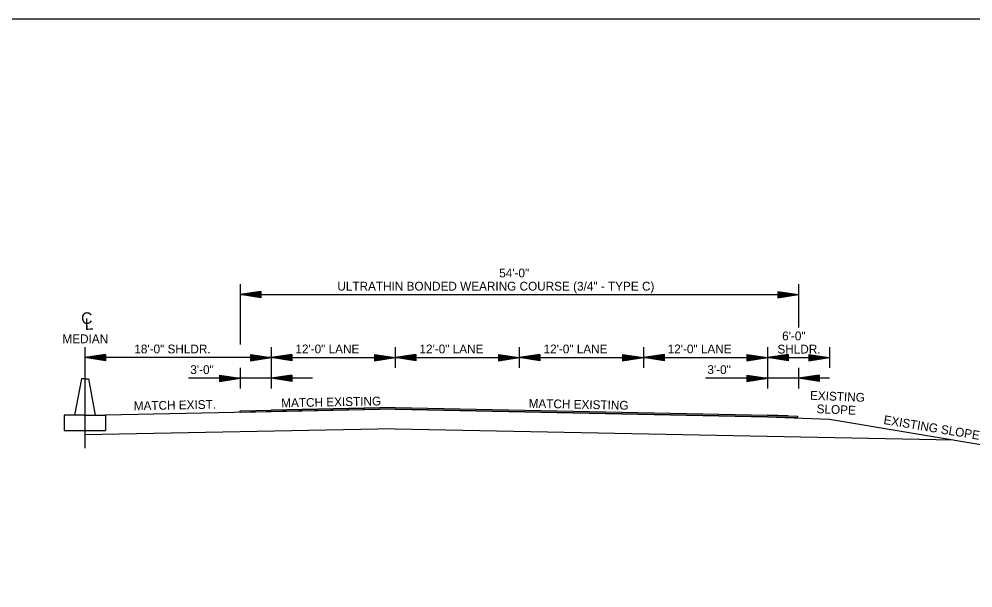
# Model space of a CAD drawing. Extents: x 2261938 to 2263136, y -3124572 to -3124216.
# Drawn here: x 2262374.3 to 2262466.5, y -3124501.1 to -3124446.1 of the extents above; entities that cross this region are included whole.
import ezdxf

# ---------------------------------------------------------------- set-up
doc = ezdxf.new("R2010")
doc.units = 0
for name, color, linetype in [('DSN_DRFT_Common-Annotations', 7, 'Continuous'), ('DSN_DRFT_Common-Line', 7, 'Continuous'), ('DSN_DRFT_Dimension', 7, 'Continuous')]:
    doc.layers.add(name, color=color, linetype=linetype)

msp = doc.modelspace()

# ---------------------------------------------------------------- linework, layer by layer
at = {"layer": 'DSN_DRFT_Common-Line'}
for p, q in [((2262395.658, -3124471.75), (2262395.658, -3124477.576)), ((2262449.658, -3124471.75), (2262449.658, -3124475.924)), ((2262380.658, -3124477.836), (2262380.658, -3124487.585)), ((2262398.658, -3124477.836), (2262398.658, -3124481.836)), ((2262410.658, -3124477.836), (2262410.658, -3124479.836)), ((2262422.658, -3124477.836), (2262422.658, -3124479.836)), ((2262434.658, -3124477.836), (2262434.658, -3124479.836)), ((2262446.658, -3124477.836), (2262446.658, -3124481.836)), ((2262452.658, -3124477.836), (2262452.658, -3124479.836)), ((2262395.658, -3124479.836), (2262395.658, -3124481.836)), ((2262398.658, -3124479.836), (2262398.658, -3124481.836)), ((2262449.658, -3124479.836), (2262449.658, -3124481.836)), ((2262380.325, -3124480.896), (2262379.658, -3124484.396)), ((2262380.658, -3124480.896), (2262380.325, -3124480.896)), ((2262380.658, -3124480.896), (2262380.991, -3124480.896)), ((2262380.991, -3124480.896), (2262381.658, -3124484.396)), ((2262410.658, -3124483.836), (2262382.658, -3124484.396)), ((2262410.658, -3124483.669), (2262398.658, -3124483.909)), ((2262410.658, -3124483.669), (2262446.658, -3124484.389)), ((2262410.658, -3124483.836), (2262446.658, -3124484.556)), ((2262380.658, -3124484.396), (2262378.658, -3124484.396)), ((2262378.658, -3124484.396), (2262378.658, -3124485.896)), ((2262380.658, -3124484.396), (2262382.658, -3124484.396)), ((2262382.658, -3124484.396), (2262382.658, -3124485.896)), ((2262446.658, -3124484.556), (2262452.658, -3124484.796)), ((2262449.551, -3124484.505), (2262449.545, -3124484.671)), ((2262452.658, -3124484.796), (2262472.658, -3124488.129)), ((2262378.658, -3124485.896), (2262382.658, -3124485.896)), ((2262410.658, -3124485.711), (2262380.658, -3124486.311)), ((2262410.658, -3124485.711), (2262464.625, -3124486.79))]:
    msp.add_line(p, q, dxfattribs=at)
for points in [[(2262328.106, -3124446.104), (2262328.106, -3124556.104), (2262498.106, -3124556.104), (2262498.106, -3124446.104)], [(2262446.658, -3124484.556), (2262410.658, -3124483.836), (2262398.658, -3124484.076), (2262395.658, -3124484.136), (2262395.658, -3124483.967), (2262398.658, -3124483.909), (2262410.658, -3124483.669), (2262446.658, -3124484.389), (2262449.551, -3124484.505), (2262449.545, -3124484.671)]]:
    msp.add_lwpolyline(points, close=True, dxfattribs=at)
msp.add_lwpolyline([(2262448.658, -3124484.469), (2262446.658, -3124484.389), (2262448.658, -3124484.469), (2262449.551, -3124484.505)], dxfattribs=at)
at = {"layer": 'DSN_DRFT_Dimension'}
for p, q in [((2262397.658, -3124472.45), (2262395.658, -3124472.75)), ((2262397.658, -3124473.05), (2262395.658, -3124472.75)), ((2262395.658, -3124472.75), (2262449.658, -3124472.75)), ((2262397.658, -3124472.5), (2262395.992, -3124472.75)), ((2262397.658, -3124473), (2262395.992, -3124472.75)), ((2262397.658, -3124472.551), (2262396.336, -3124472.75)), ((2262397.658, -3124472.949), (2262396.336, -3124472.75)), ((2262397.658, -3124472.601), (2262396.669, -3124472.75)), ((2262397.658, -3124472.899), (2262396.669, -3124472.75)), ((2262397.658, -3124472.653), (2262397.008, -3124472.75)), ((2262397.658, -3124472.848), (2262397.008, -3124472.75)), ((2262397.658, -3124472.703), (2262397.342, -3124472.75)), ((2262397.658, -3124472.797), (2262397.342, -3124472.75)), ((2262397.658, -3124472.45), (2262397.658, -3124473.05)), ((2262447.658, -3124472.45), (2262449.658, -3124472.75)), ((2262447.658, -3124472.45), (2262447.658, -3124473.05)), ((2262447.658, -3124472.5), (2262449.324, -3124472.75)), ((2262447.658, -3124472.551), (2262448.98, -3124472.75)), ((2262447.658, -3124472.601), (2262448.647, -3124472.75)), ((2262447.658, -3124472.653), (2262448.308, -3124472.75)), ((2262447.658, -3124472.703), (2262447.974, -3124472.75)), ((2262447.658, -3124473.05), (2262449.658, -3124472.75)), ((2262447.658, -3124472.848), (2262448.308, -3124472.75)), ((2262447.658, -3124472.949), (2262448.98, -3124472.75)), ((2262447.658, -3124473), (2262449.324, -3124472.75)), ((2262447.658, -3124472.899), (2262448.647, -3124472.75)), ((2262447.658, -3124472.797), (2262447.974, -3124472.75)), ((2262382.658, -3124478.536), (2262380.658, -3124478.836)), ((2262398.658, -3124478.836), (2262380.658, -3124478.836)), ((2262382.658, -3124479.136), (2262380.658, -3124478.836)), ((2262382.658, -3124478.586), (2262380.992, -3124478.836)), ((2262382.658, -3124479.086), (2262380.992, -3124478.836)), ((2262382.658, -3124478.637), (2262381.336, -3124478.836)), ((2262382.658, -3124479.035), (2262381.336, -3124478.836)), ((2262382.658, -3124478.687), (2262381.669, -3124478.836)), ((2262382.658, -3124478.985), (2262381.669, -3124478.836)), ((2262382.658, -3124478.739), (2262382.008, -3124478.836)), ((2262382.658, -3124478.934), (2262382.008, -3124478.836)), ((2262382.658, -3124478.789), (2262382.342, -3124478.836)), ((2262382.658, -3124478.883), (2262382.342, -3124478.836)), ((2262382.658, -3124478.536), (2262382.658, -3124479.136)), ((2262396.658, -3124478.536), (2262398.658, -3124478.836)), ((2262396.658, -3124478.536), (2262396.658, -3124479.136)), ((2262396.658, -3124478.586), (2262398.324, -3124478.836)), ((2262396.658, -3124478.637), (2262397.98, -3124478.836)), ((2262396.658, -3124478.687), (2262397.647, -3124478.836)), ((2262396.658, -3124478.739), (2262397.308, -3124478.836)), ((2262396.658, -3124478.789), (2262396.974, -3124478.836)), ((2262396.658, -3124479.136), (2262398.658, -3124478.836)), ((2262396.658, -3124478.934), (2262397.308, -3124478.836)), ((2262396.658, -3124479.035), (2262397.98, -3124478.836)), ((2262396.658, -3124479.086), (2262398.324, -3124478.836)), ((2262396.658, -3124478.985), (2262397.647, -3124478.836)), ((2262396.658, -3124478.883), (2262396.974, -3124478.836)), ((2262400.658, -3124478.536), (2262398.658, -3124478.836)), ((2262398.658, -3124478.836), (2262410.658, -3124478.836)), ((2262400.658, -3124479.136), (2262398.658, -3124478.836)), ((2262400.658, -3124478.586), (2262398.992, -3124478.836)), ((2262400.658, -3124479.086), (2262398.992, -3124478.836)), ((2262400.658, -3124478.637), (2262399.336, -3124478.836)), ((2262400.658, -3124479.035), (2262399.336, -3124478.836)), ((2262400.658, -3124478.687), (2262399.669, -3124478.836)), ((2262400.658, -3124478.985), (2262399.669, -3124478.836)), ((2262400.658, -3124478.739), (2262400.008, -3124478.836)), ((2262400.658, -3124478.934), (2262400.008, -3124478.836)), ((2262400.658, -3124478.789), (2262400.342, -3124478.836)), ((2262400.658, -3124478.883), (2262400.342, -3124478.836)), ((2262400.658, -3124478.536), (2262400.658, -3124479.136)), ((2262408.658, -3124478.536), (2262410.658, -3124478.836)), ((2262408.658, -3124478.536), (2262408.658, -3124479.136)), ((2262408.658, -3124478.586), (2262410.324, -3124478.836)), ((2262408.658, -3124478.637), (2262409.98, -3124478.836)), ((2262408.658, -3124478.687), (2262409.647, -3124478.836)), ((2262408.658, -3124478.739), (2262409.308, -3124478.836)), ((2262408.658, -3124478.789), (2262408.974, -3124478.836)), ((2262408.658, -3124479.136), (2262410.658, -3124478.836)), ((2262408.658, -3124478.934), (2262409.308, -3124478.836)), ((2262408.658, -3124479.035), (2262409.98, -3124478.836)), ((2262408.658, -3124479.086), (2262410.324, -3124478.836)), ((2262408.658, -3124478.985), (2262409.647, -3124478.836)), ((2262408.658, -3124478.883), (2262408.974, -3124478.836)), ((2262412.658, -3124478.536), (2262410.658, -3124478.836)), ((2262410.658, -3124478.836), (2262422.658, -3124478.836)), ((2262412.658, -3124479.136), (2262410.658, -3124478.836)), ((2262412.658, -3124478.586), (2262410.992, -3124478.836)), ((2262412.658, -3124479.086), (2262410.992, -3124478.836)), ((2262412.658, -3124478.637), (2262411.336, -3124478.836)), ((2262412.658, -3124479.035), (2262411.336, -3124478.836)), ((2262412.658, -3124478.687), (2262411.669, -3124478.836)), ((2262412.658, -3124478.985), (2262411.669, -3124478.836)), ((2262412.658, -3124478.739), (2262412.008, -3124478.836)), ((2262412.658, -3124478.934), (2262412.008, -3124478.836)), ((2262412.658, -3124478.789), (2262412.342, -3124478.836)), ((2262412.658, -3124478.883), (2262412.342, -3124478.836)), ((2262412.658, -3124478.536), (2262412.658, -3124479.136)), ((2262420.658, -3124478.536), (2262422.658, -3124478.836)), ((2262420.658, -3124478.536), (2262420.658, -3124479.136)), ((2262420.658, -3124478.586), (2262422.324, -3124478.836)), ((2262420.658, -3124478.637), (2262421.98, -3124478.836)), ((2262420.658, -3124478.687), (2262421.647, -3124478.836)), ((2262420.658, -3124478.739), (2262421.308, -3124478.836)), ((2262420.658, -3124478.789), (2262420.974, -3124478.836)), ((2262420.658, -3124479.136), (2262422.658, -3124478.836)), ((2262420.658, -3124478.934), (2262421.308, -3124478.836)), ((2262420.658, -3124479.035), (2262421.98, -3124478.836)), ((2262420.658, -3124479.086), (2262422.324, -3124478.836)), ((2262420.658, -3124478.985), (2262421.647, -3124478.836)), ((2262420.658, -3124478.883), (2262420.974, -3124478.836)), ((2262424.658, -3124478.536), (2262422.658, -3124478.836)), ((2262422.658, -3124478.836), (2262434.658, -3124478.836)), ((2262424.658, -3124479.136), (2262422.658, -3124478.836)), ((2262424.658, -3124478.586), (2262422.992, -3124478.836)), ((2262424.658, -3124479.086), (2262422.992, -3124478.836)), ((2262424.658, -3124478.637), (2262423.336, -3124478.836)), ((2262424.658, -3124479.035), (2262423.336, -3124478.836)), ((2262424.658, -3124478.687), (2262423.669, -3124478.836)), ((2262424.658, -3124478.985), (2262423.669, -3124478.836)), ((2262424.658, -3124478.739), (2262424.008, -3124478.836)), ((2262424.658, -3124478.934), (2262424.008, -3124478.836)), ((2262424.658, -3124478.789), (2262424.342, -3124478.836)), ((2262424.658, -3124478.883), (2262424.342, -3124478.836)), ((2262424.658, -3124478.536), (2262424.658, -3124479.136)), ((2262432.658, -3124478.536), (2262434.658, -3124478.836)), ((2262432.658, -3124478.536), (2262432.658, -3124479.136)), ((2262432.658, -3124478.586), (2262434.324, -3124478.836)), ((2262432.658, -3124478.637), (2262433.98, -3124478.836)), ((2262432.658, -3124478.687), (2262433.647, -3124478.836)), ((2262432.658, -3124478.739), (2262433.308, -3124478.836)), ((2262432.658, -3124478.789), (2262432.974, -3124478.836)), ((2262432.658, -3124479.136), (2262434.658, -3124478.836)), ((2262432.658, -3124478.934), (2262433.308, -3124478.836)), ((2262432.658, -3124479.035), (2262433.98, -3124478.836)), ((2262432.658, -3124479.086), (2262434.324, -3124478.836)), ((2262432.658, -3124478.985), (2262433.647, -3124478.836)), ((2262432.658, -3124478.883), (2262432.974, -3124478.836)), ((2262436.658, -3124478.536), (2262434.658, -3124478.836)), ((2262434.658, -3124478.836), (2262446.658, -3124478.836)), ((2262436.658, -3124479.136), (2262434.658, -3124478.836)), ((2262436.658, -3124478.586), (2262434.992, -3124478.836)), ((2262436.658, -3124479.086), (2262434.992, -3124478.836)), ((2262436.658, -3124478.637), (2262435.336, -3124478.836)), ((2262436.658, -3124479.035), (2262435.336, -3124478.836)), ((2262436.658, -3124478.687), (2262435.669, -3124478.836)), ((2262436.658, -3124478.985), (2262435.669, -3124478.836)), ((2262436.658, -3124478.739), (2262436.008, -3124478.836)), ((2262436.658, -3124478.934), (2262436.008, -3124478.836)), ((2262436.658, -3124478.789), (2262436.342, -3124478.836)), ((2262436.658, -3124478.883), (2262436.342, -3124478.836)), ((2262436.658, -3124478.536), (2262436.658, -3124479.136)), ((2262444.658, -3124478.536), (2262446.658, -3124478.836)), ((2262444.658, -3124478.536), (2262444.658, -3124479.136)), ((2262444.658, -3124478.586), (2262446.324, -3124478.836)), ((2262444.658, -3124478.637), (2262445.98, -3124478.836)), ((2262444.658, -3124478.687), (2262445.647, -3124478.836)), ((2262444.658, -3124478.739), (2262445.308, -3124478.836)), ((2262444.658, -3124478.789), (2262444.974, -3124478.836)), ((2262444.658, -3124479.136), (2262446.658, -3124478.836)), ((2262444.658, -3124478.934), (2262445.308, -3124478.836)), ((2262444.658, -3124479.035), (2262445.98, -3124478.836)), ((2262444.658, -3124479.086), (2262446.324, -3124478.836)), ((2262444.658, -3124478.985), (2262445.647, -3124478.836)), ((2262444.658, -3124478.883), (2262444.974, -3124478.836)), ((2262448.658, -3124478.536), (2262446.658, -3124478.836)), ((2262446.658, -3124478.836), (2262452.658, -3124478.836)), ((2262448.658, -3124479.136), (2262446.658, -3124478.836)), ((2262448.658, -3124478.586), (2262446.992, -3124478.836)), ((2262448.658, -3124479.086), (2262446.992, -3124478.836)), ((2262448.658, -3124478.637), (2262447.336, -3124478.836)), ((2262448.658, -3124479.035), (2262447.336, -3124478.836)), ((2262448.658, -3124478.687), (2262447.669, -3124478.836)), ((2262448.658, -3124478.985), (2262447.669, -3124478.836)), ((2262448.658, -3124478.739), (2262448.008, -3124478.836)), ((2262448.658, -3124478.934), (2262448.008, -3124478.836)), ((2262448.658, -3124478.789), (2262448.342, -3124478.836)), ((2262448.658, -3124478.883), (2262448.342, -3124478.836)), ((2262448.658, -3124478.536), (2262448.658, -3124479.136)), ((2262450.658, -3124478.536), (2262452.658, -3124478.836)), ((2262450.658, -3124478.536), (2262450.658, -3124479.136)), ((2262450.658, -3124478.586), (2262452.324, -3124478.836)), ((2262450.658, -3124478.637), (2262451.98, -3124478.836)), ((2262450.658, -3124478.687), (2262451.647, -3124478.836)), ((2262450.658, -3124478.739), (2262451.308, -3124478.836)), ((2262450.658, -3124478.789), (2262450.974, -3124478.836)), ((2262450.658, -3124479.136), (2262452.658, -3124478.836)), ((2262450.658, -3124478.934), (2262451.308, -3124478.836)), ((2262450.658, -3124479.035), (2262451.98, -3124478.836)), ((2262450.658, -3124479.086), (2262452.324, -3124478.836)), ((2262450.658, -3124478.985), (2262451.647, -3124478.836)), ((2262450.658, -3124478.883), (2262450.974, -3124478.836)), ((2262402.658, -3124480.836), (2262390.658, -3124480.836)), ((2262393.658, -3124480.536), (2262395.658, -3124480.836)), ((2262393.658, -3124480.536), (2262393.658, -3124481.136)), ((2262393.658, -3124480.586), (2262395.324, -3124480.836)), ((2262393.658, -3124480.637), (2262394.98, -3124480.836)), ((2262393.658, -3124480.687), (2262394.647, -3124480.836)), ((2262393.658, -3124480.739), (2262394.308, -3124480.836)), ((2262393.658, -3124480.789), (2262393.974, -3124480.836)), ((2262393.658, -3124481.136), (2262395.658, -3124480.836)), ((2262393.658, -3124480.934), (2262394.308, -3124480.836)), ((2262393.658, -3124481.035), (2262394.98, -3124480.836)), ((2262393.658, -3124481.086), (2262395.324, -3124480.836)), ((2262393.658, -3124480.985), (2262394.647, -3124480.836)), ((2262393.658, -3124480.883), (2262393.974, -3124480.836)), ((2262400.658, -3124480.536), (2262398.658, -3124480.836)), ((2262400.658, -3124481.136), (2262398.658, -3124480.836)), ((2262400.658, -3124480.586), (2262398.992, -3124480.836)), ((2262400.658, -3124481.086), (2262398.992, -3124480.836)), ((2262400.658, -3124480.637), (2262399.336, -3124480.836)), ((2262400.658, -3124481.035), (2262399.336, -3124480.836)), ((2262400.658, -3124480.687), (2262399.669, -3124480.836)), ((2262400.658, -3124480.985), (2262399.669, -3124480.836)), ((2262400.658, -3124480.739), (2262400.008, -3124480.836)), ((2262400.658, -3124480.934), (2262400.008, -3124480.836)), ((2262400.658, -3124480.789), (2262400.342, -3124480.836)), ((2262400.658, -3124480.883), (2262400.342, -3124480.836)), ((2262400.658, -3124480.536), (2262400.658, -3124481.136)), ((2262452.658, -3124480.836), (2262440.658, -3124480.836)), ((2262444.658, -3124480.536), (2262446.658, -3124480.836)), ((2262444.658, -3124480.536), (2262444.658, -3124481.136)), ((2262444.658, -3124480.586), (2262446.324, -3124480.836)), ((2262444.658, -3124480.637), (2262445.98, -3124480.836)), ((2262444.658, -3124480.687), (2262445.647, -3124480.836)), ((2262444.658, -3124480.739), (2262445.308, -3124480.836)), ((2262444.658, -3124480.789), (2262444.974, -3124480.836)), ((2262444.658, -3124481.136), (2262446.658, -3124480.836)), ((2262444.658, -3124480.934), (2262445.308, -3124480.836)), ((2262444.658, -3124481.035), (2262445.98, -3124480.836)), ((2262444.658, -3124481.086), (2262446.324, -3124480.836)), ((2262444.658, -3124480.985), (2262445.647, -3124480.836)), ((2262444.658, -3124480.883), (2262444.974, -3124480.836)), ((2262451.658, -3124480.536), (2262449.658, -3124480.836)), ((2262451.658, -3124481.136), (2262449.658, -3124480.836)), ((2262451.658, -3124480.586), (2262449.992, -3124480.836)), ((2262451.658, -3124481.086), (2262449.992, -3124480.836)), ((2262451.658, -3124480.637), (2262450.336, -3124480.836)), ((2262451.658, -3124481.035), (2262450.336, -3124480.836)), ((2262451.658, -3124480.687), (2262450.669, -3124480.836)), ((2262451.658, -3124480.985), (2262450.669, -3124480.836)), ((2262451.658, -3124480.739), (2262451.008, -3124480.836)), ((2262451.658, -3124480.934), (2262451.008, -3124480.836)), ((2262451.658, -3124480.789), (2262451.342, -3124480.836)), ((2262451.658, -3124480.883), (2262451.342, -3124480.836)), ((2262451.658, -3124480.536), (2262451.658, -3124481.136))]:
    msp.add_line(p, q, dxfattribs=at)

# ---------------------------------------------------------------- texts
at = {"layer": 'DSN_DRFT_Common-Annotations'}
for s, p in [('54\'-0"', (2262420.721, -3124471.08)), ('ULTRATHIN BONDED WEARING COURSE (3/4" - TYPE C)', (2262405.069, -3124472.355)), ('MEDIAN', (2262378.482, -3124477.446)), ('6\'-0" ', (2262448.082, -3124477.166)), ('18\'-0" SHLDR.', (2262385.435, -3124478.426)), ('12\'-0" LANE', (2262401.011, -3124478.426)), ('12\'-0" LANE', (2262413.011, -3124478.426)), ('12\'-0" LANE', (2262425.011, -3124478.426)), ('12\'-0" LANE', (2262437.011, -3124478.426)), ('SHLDR.', (2262447.624, -3124478.441)), (' 3\'-0"', (2262390.533, -3124480.426)), (' 3\'-0"', (2262440.533, -3124480.426))]:
    msp.add_text(s, height=0.85, dxfattribs=at).set_placement(p)
for s, height, rotation, p in [('C', 1.124, 1.14576, (2262380.301, -3124475.591)), ('L', 1.124, 1.14576, (2262380.651, -3124476.156)), ('EXISTING ', 0.85, 357.70939, (2262450.761, -3124482.905)), ('MATCH EXIST.', 0.85, 1.14576, (2262385.387, -3124483.931)), ('MATCH EXISTING', 0.85, 1.14576, (2262399.648, -3124483.646)), ('MATCH EXISTING', 0.85, 358.85424, (2262423.557, -3124483.684)), ('SLOPE', 0.85, 357.70939, (2262451.402, -3124484.207)), ('EXISTING SLOPE', 0.85, 350.538, (2262457.84, -3124485.244))]:
    msp.add_text(s, height=height, rotation=rotation, dxfattribs=at).set_placement(p)

doc.saveas('drawing.dxf')
